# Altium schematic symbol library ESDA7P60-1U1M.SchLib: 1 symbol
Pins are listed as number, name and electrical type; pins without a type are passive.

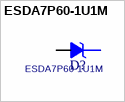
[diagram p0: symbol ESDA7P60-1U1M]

## ESDA7P60-1U1M
designator D?
footprint ST_1610
pins: 1 K, 2 A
